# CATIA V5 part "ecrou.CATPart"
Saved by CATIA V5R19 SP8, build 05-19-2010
Part number: ecrou
Bounding box of the stored display mesh (mm): x -17.5 to 17.5, y -10 to 10, z -9.942 to 9.942
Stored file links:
  G:\EU_thinkMotion\CFAO_2010\MMS_groupe3\MMS_groupe3\A reprendre\mmugnier\Systeme_Cric_Y\Systeme_Cric_Y\ecrou.CATPart
  C:\Users\matthieu\Desktop\CFAO\Systeme_Cric_Y\Cric_Y.CATProduct
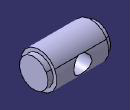
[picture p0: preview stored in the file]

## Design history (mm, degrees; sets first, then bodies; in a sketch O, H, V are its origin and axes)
Set1
  Plane1 "Plan exter gauche": linked copy from another document
  Plane2 "Plan inter gauche": linked copy from another document
  Plane3 "Plan inter droit": linked copy from another document
  Plane4 "Plan exter droit": linked copy from another document
  Line1 "Axe 3": linked copy from another document
  Line2 "Axe liaison helicoidale": linked copy from another document
Body1 (main body)
  Sketch1 on xy-plane, origin (0, 0, 0), H (1, 0, 0), V (0, 1, 0)
    line L1 (-14.5, 10) -> (14.5, 10)
    line L2 (14.5, 10) -> (14.5, 8)
    line L3 (14.5, 8) -> (17.5, 8)
    line L4 (17.5, 8) -> (17.5, 0)
    point P5 (17.5, 0)
    line L5 (17.5, 0) -> (-17.5, 0)
    line L6 (-17.5, 0) -> (-17.5, 8)
    line L7 (-17.5, 8) -> (-14.5, 8)
    point P8 (-14.5, 8)
    line L8 (-14.5, 8) -> (-14.5, 10)
    reference intersected line E1 through (17.5, 0) direction (0, 1) from Plane1
    reference intersected line E2 through (14.5, 0) direction (0, 1) from Plane2
    reference intersected line E3 through (-14.5, 0) direction (0, 1) from Plane3
    reference intersected line E4 through (-17.5, 0) direction (0, 1) from Plane4
    length L4 = 8
    distance L1 L3 = 2
    horizontal: L1 H, L3 H, L5 H, L7 H
    vertical: L2 V, L4 V, L6 V, L8 V
    coincidence: P5 H, L3 L7, L4 E1, E2 L2, P8 E3, L6 E4
  Shaft1: profile Sketch1, axis Line1, angle 360
  Sketch2 on xy-plane, origin (0, 0, 0), H (1, 0, 0), V (0, 1, 0)
    point P1 (0, -10)
    line L1 (0, -10) -> (5, -10)
    line L2 (5, -10) -> (5, 10)
    line L3 (5, 10) -> (0, 10)
    line L4 (0, 10) -> (0, -10)
    reference projected line E1 (-100, 0) -> (100, 0) from Line1
    length L3 = 5
    distance L3 E1 = 10
    length L2 = 20
    coincidence: P1 V
    horizontal: L1 H, L3 H
    vertical: L2 V, L4 V
  Groove1: profile Sketch2, axis Line2, angle 360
